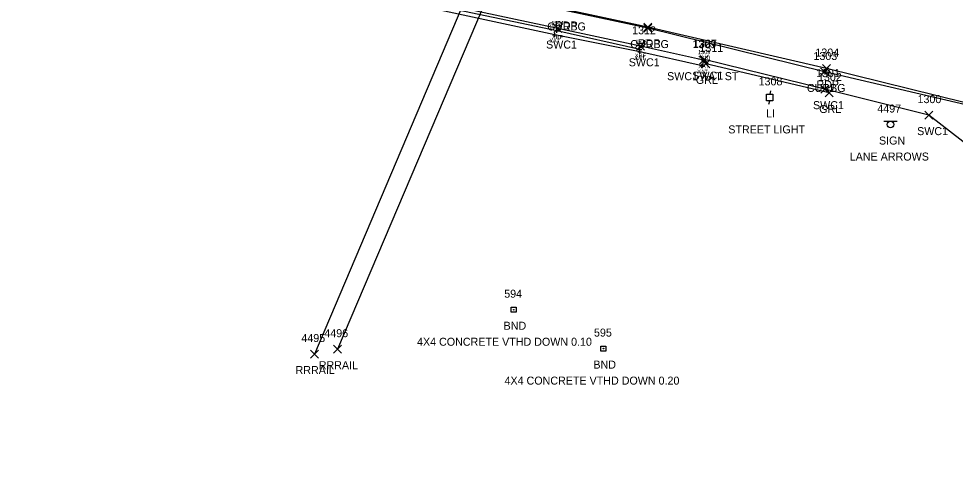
# Model space of a CAD drawing. Extents: x 1690689 to 1696275, y 438760 to 444007.
# Drawn here: x 1692595.1 to 1692829.1, y 438782.1 to 438892.2 of the extents above; entities that cross this region are included whole.
import ezdxf

# ---------------------------------------------------------------- set-up
doc = ezdxf.new("R2010")
doc.units = 0
for name, color, linetype in [('B_A', 7, 'Continuous'), ('B_I', 7, 'Continuous'), ('B_TIC', 7, 'Continuous'), ('BR', 7, 'Continuous'), ('BSUBM', 7, 'Continuous'), ('Level 18', 7, 'Continuous'), ('M_A', 7, 'Continuous'), ('M_C', 7, 'Continuous'), ('M_I', 7, 'Continuous'), ('P_A', 7, 'Continuous'), ('P_I', 7, 'Continuous'), ('P_TIC', 7, 'Continuous'), ('PET', 7, 'Continuous'), ('R_A', 7, 'Continuous'), ('R_I', 7, 'Continuous'), ('R_TIC', 7, 'Continuous'), ('RC', 7, 'Continuous'), ('RGR', 7, 'Continuous'), ('RR', 7, 'Continuous'), ('RSW', 7, 'Continuous'), ('S_A', 7, 'Continuous'), ('S_C', 7, 'Continuous'), ('S_I', 7, 'Continuous'), ('SSGN', 7, 'Continuous'), ('U_A', 7, 'Continuous'), ('U_C', 7, 'Continuous'), ('U_I', 7, 'Continuous'), ('ULP', 7, 'Continuous')]:
    doc.layers.add(name, color=color, linetype=linetype)

msp = doc.modelspace()

# ---------------------------------------------------------------- linework, layer by layer
at = {"layer": 'B_TIC'}
for p, q in [((1692729.04, 438888.19), (1692729.12, 438888.19)), ((1692729.59, 438889.17), (1692729.66, 438889.17)), ((1692750.32, 438884.51), (1692750.39, 438884.51)), ((1692750.29, 438883.93), (1692750.37, 438883.93)), ((1692765.92, 438880.45), (1692766, 438880.45)), ((1692766.24, 438881.85), (1692766.31, 438881.85))]:
    msp.add_line(p, q, dxfattribs=at)
for points in [[(1692729.58, 438888.67), (1692729.58, 438889.67)], [(1692728.54, 438888.19), (1692729.54, 438888.19)], [(1692729.04, 438887.69), (1692729.04, 438888.69)], [(1692729.08, 438889.17), (1692730.08, 438889.17)], [(1692749.81, 438884.51), (1692750.81, 438884.51)], [(1692750.31, 438884.01), (1692750.31, 438885.01)], [(1692749.79, 438883.93), (1692750.79, 438883.93)], [(1692750.29, 438883.43), (1692750.29, 438884.43)], [(1692766.23, 438881.35), (1692766.23, 438882.35)], [(1692765.42, 438880.45), (1692766.42, 438880.45)], [(1692765.73, 438881.85), (1692766.73, 438881.85)], [(1692765.92, 438879.95), (1692765.92, 438880.95)]]:
    msp.add_lwpolyline(points, dxfattribs=at)
at = {"layer": 'BR'}
msp.add_lwpolyline([(1692750.31, 438884.51), (1692729.58, 438889.17), (1692656.82, 438904.54), (1692638.24, 438908.3)], dxfattribs=at)
at = {"layer": 'BSUBM'}
msp.add_lwpolyline([(1692766.23, 438881.85), (1692765.92, 438880.45), (1692750.29, 438883.93), (1692729.04, 438888.19), (1692656.49, 438903.81), (1692637.77, 438907.81), (1692638.39, 438910.1)], dxfattribs=at)
at = {"layer": 'Level 18'}
for points in [[(1692718.17, 438820.12), (1692719.42, 438820.12), (1692719.42, 438818.87), (1692718.17, 438818.87)], [(1692740.6, 438810.41), (1692741.85, 438810.41), (1692741.85, 438809.16), (1692740.6, 438809.16)]]:
    msp.add_lwpolyline(points, close=True, dxfattribs=at)
for centre in [(1692718.8, 438819.5), (1692741.22, 438809.79)]:
    msp.add_circle(centre, 0.0833, dxfattribs=at)
at = {"layer": 'P_TIC'}
for points in [[(1692751.35, 438889.07), (1692753.35, 438891.07)], [(1692753.35, 438889.07), (1692751.35, 438891.07)], [(1692795.94, 438878.76), (1692797.94, 438880.76)], [(1692797.94, 438878.76), (1692795.94, 438880.76)]]:
    msp.add_lwpolyline(points, dxfattribs=at)
at = {"layer": 'PET'}
msp.add_lwpolyline([(1693167.67, 438782.57), (1693141.53, 438790.2), (1693112.15, 438798.3), (1693087.86, 438805.04), (1693057.06, 438813.51), (1693019.12, 438823.55), (1692973.09, 438835.84), (1692924.99, 438847.57), (1692878.5, 438859.29), (1692838.41, 438869.51), (1692796.94, 438879.76), (1692752.35, 438890.07), (1692731.67, 438894.52), (1692658.1, 438910.21), (1692638.65, 438914.4), (1692605.27, 438921.45), (1692561.1, 438930.73), (1692527.61, 438937.28), (1692485.07, 438945.57), (1692435.03, 438955.4)], dxfattribs=at)
at = {"layer": 'R_TIC'}
for points in [[(1692728.84, 438888.75), (1692730.84, 438890.75)], [(1692730.84, 438888.75), (1692728.84, 438890.75)], [(1692751.32, 438888.87), (1692753.32, 438890.87)], [(1692753.32, 438888.87), (1692751.32, 438890.87)], [(1692749.5, 438884.32), (1692751.5, 438886.32)], [(1692751.5, 438884.32), (1692749.5, 438886.32)], [(1692765.23, 438880.85), (1692767.23, 438882.85)], [(1692767.23, 438880.85), (1692765.23, 438882.85)], [(1692765.39, 438880.99), (1692767.39, 438882.99)], [(1692767.39, 438880.99), (1692765.39, 438882.99)], [(1692765.77, 438879.92), (1692767.77, 438881.92)], [(1692767.77, 438879.92), (1692765.77, 438881.92)], [(1692795.47, 438877.9), (1692797.47, 438879.9)], [(1692797.47, 438877.9), (1692795.47, 438879.9)], [(1692795.53, 438873.61), (1692797.53, 438875.61)], [(1692797.53, 438873.61), (1692795.53, 438875.61)], [(1692796.58, 438872.66), (1692798.58, 438874.66)], [(1692798.58, 438872.66), (1692796.58, 438874.66)], [(1692821.55, 438867.12), (1692823.55, 438869.12)], [(1692823.55, 438867.12), (1692821.55, 438869.12)], [(1692673.8, 438808.64), (1692675.8, 438810.64)], [(1692675.8, 438808.64), (1692673.8, 438810.64)], [(1692668.01, 438807.43), (1692670.01, 438809.43)], [(1692670.01, 438807.43), (1692668.01, 438809.43)]]:
    msp.add_lwpolyline(points, dxfattribs=at)
at = {"layer": 'RC'}
msp.add_lwpolyline([(1693167.44, 438782.14), (1693141.42, 438789.93), (1693119.24, 438796.02), (1693112.17, 438798), (1693087.95, 438804.88), (1693056.95, 438813.29), (1693019.1, 438823.35), (1692973.04, 438835.52), (1692925.29, 438847.1), (1692878.46, 438858.86), (1692838.19, 438869.18), (1692796.47, 438878.9), (1692752.32, 438889.87), (1692731.59, 438894.27), (1692657.89, 438909.92), (1692639.33, 438913.93), (1692605.34, 438921.22), (1692561.27, 438930.49), (1692527.54, 438937.1), (1692485.06, 438945.4), (1692435.02, 438955.15)], dxfattribs=at)
at = {"layer": 'RGR'}
msp.add_lwpolyline([(1692797.58, 438873.66), (1692766.77, 438880.92)], dxfattribs=at)
at = {"layer": 'RR'}
for points in [[(1692774.79, 439057.61), (1692669.01, 438808.43)], [(1692779.19, 439055.14), (1692674.8, 438809.64)]]:
    msp.add_lwpolyline(points, dxfattribs=at)
at = {"layer": 'RSW'}
msp.add_lwpolyline([(1692961.7, 438815.71), (1692965.05, 438825.1), (1692922.46, 438836.11), (1692875.99, 438847.64), (1692836.17, 438857.54), (1692822.55, 438868.12), (1692796.53, 438874.61), (1692766.39, 438881.99), (1692766.23, 438881.85), (1692750.5, 438885.32), (1692729.84, 438889.75), (1692656.64, 438905.41), (1692656.72, 438906.14), (1692638.39, 438910.1), (1692639.33, 438913.93)], dxfattribs=at)
at = {"layer": 'SSGN'}
for p, q in [((1692811.27, 438866.62), (1692814.61, 438866.62)), ((1692812.92, 438865.79), (1692812.92, 438865.79))]:
    msp.add_line(p, q, dxfattribs=at)
msp.add_circle((1692812.92, 438865.79), 0.833, dxfattribs=at)
at = {"layer": 'ULP'}
for p, q in [((1692781.92, 438871.72), (1692781.92, 438873.39)), ((1692781.92, 438873.39), (1692783.58, 438873.39)), ((1692782.92, 438874.22), (1692782.75, 438873.39)), ((1692783.58, 438873.39), (1692783.58, 438871.72)), ((1692783.58, 438871.72), (1692781.92, 438871.72)), ((1692782.5, 438870.89), (1692782.75, 438871.72)), ((1692782.75, 438872.55), (1692782.75, 438872.55))]:
    msp.add_line(p, q, dxfattribs=at)

# ---------------------------------------------------------------- texts
at = {"layer": 'B_A'}
for s, p in [('XAT', (1692727.74, 438886.19)), ('XRF', (1692728.34, 438887.17)), ('XAT', (1692748.99, 438881.93)), ('XRF', (1692749.07, 438882.51)), ('XAT', (1692764.94, 438879.85)), ('XAT', (1692764.63, 438878.45))]:
    msp.add_text(s, height=1, dxfattribs=at).set_placement(p)
at = {"layer": 'B_I'}
for s, p in [('1504', (1692728.2, 438890.67)), ('1505', (1692727.65, 438889.69)), ('1315', (1692749.25, 438886.01)), ('1314', (1692749.22, 438885.43)), ('1310', (1692764.81, 438881.95)), ('1309', (1692764.85, 438883.35))]:
    msp.add_text(s, height=1, dxfattribs=at).set_placement(p)
at = {"layer": 'M_A'}
for p in [(1692716.28, 438814.5), (1692738.71, 438804.79)]:
    msp.add_text('BND', height=2, dxfattribs=at).set_placement(p)
at = {"layer": 'M_C'}
for s, p in [('4X4 CONCRETE VTHD DOWN 0.10', (1692694.65, 438810.5)), ('4X4 CONCRETE VTHD DOWN 0.20', (1692716.51, 438800.79))]:
    msp.add_text(s, height=2, dxfattribs=at).set_placement(p)
at = {"layer": 'M_I'}
for s, p in [('594', (1692716.43, 438822.5)), ('595', (1692738.86, 438812.79))]:
    msp.add_text(s, height=2, dxfattribs=at).set_placement(p)
at = {"layer": 'P_A'}
for p in [(1692729.15, 438889.52), (1692749.83, 438885.07), (1692794.43, 438874.76)]:
    msp.add_text('RDP', height=2, dxfattribs=at).set_placement(p)
at = {"layer": 'P_I'}
msp.add_text('1304', height=2, dxfattribs=at).set_placement((1692794.17, 438882.76))
at = {"layer": 'R_A'}
for s, p in [('CURBG', (1692727.17, 438889.27)), ('CURBG', (1692747.91, 438884.87)), ('SWC1', (1692726.88, 438884.75)), ('SWC1', (1692747.54, 438880.32)), ('SWC1 XAT ST', (1692757.12, 438876.85)), ('SWC1', (1692763.43, 438876.99)), ('GRL', (1692764.31, 438875.92)), ('CURBG', (1692792.05, 438873.9)), ('SWC1', (1692793.57, 438869.61)), ('GRL', (1692795.12, 438868.66)), ('SWC1', (1692819.59, 438863.12)), ('RRRAIL', (1692664.3, 438803.43)), ('RRRAIL', (1692670.1, 438804.64))]:
    msp.add_text(s, height=2, dxfattribs=at).set_placement(p)
at = {"layer": 'R_I'}
for s, p in [('1312', (1692748.38, 438888.32)), ('1309', (1692763.46, 438884.85)), ('1307', (1692763.61, 438884.99)), ('1311', (1692765.21, 438883.92)), ('1303', (1692793.69, 438881.9)), ('1301', (1692794.33, 438877.61)), ('1302', (1692794.81, 438876.66)), ('1300', (1692819.69, 438871.12)), ('4496', (1692671.49, 438812.64)), ('4495', (1692665.75, 438811.43))]:
    msp.add_text(s, height=2, dxfattribs=at).set_placement(p)
at = {"layer": 'S_A'}
msp.add_text('SIGN', height=2, dxfattribs=at).set_placement((1692810.06, 438860.77))
at = {"layer": 'S_C'}
msp.add_text('LANE ARROWS', height=2, dxfattribs=at).set_placement((1692802.76, 438856.77))
at = {"layer": 'S_I'}
msp.add_text('4497', height=2, dxfattribs=at).set_placement((1692809.64, 438868.77))
at = {"layer": 'U_A'}
msp.add_text('LI', height=2, dxfattribs=at).set_placement((1692781.85, 438867.55))
at = {"layer": 'U_C'}
msp.add_text('STREET LIGHT', height=2, dxfattribs=at).set_placement((1692772.41, 438863.55))
at = {"layer": 'U_I'}
msp.add_text('1308', height=2, dxfattribs=at).set_placement((1692779.98, 438875.55))

doc.saveas('drawing.dxf')
